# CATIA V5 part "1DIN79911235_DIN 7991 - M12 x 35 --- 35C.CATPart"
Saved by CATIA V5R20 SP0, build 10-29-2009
Part number: 1DIN79911235_DIN 7991 - M12 x 35 --- 35C
Revision: ANY
Definition: UNKNOWN
Nomenclature: 1DIN79911235_DIN 7991 - M12 x 35 --- 35C
Source: Unknown
Bounding box of the stored display mesh (mm): x 0 to 35, y -11.562 to 11.562, z -11.74 to 11.74
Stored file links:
  C:\Users\Utente\Desktop\IO LAVORO\3D X SITO CF\CUMSA\3D files RC\RC 328012\1DIN79911235_DIN 7991 - M12 x 35 --- 35C.CATPart
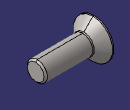
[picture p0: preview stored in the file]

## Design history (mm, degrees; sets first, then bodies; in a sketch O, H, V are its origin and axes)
Body1 "Hex" (main body)
  Solid1: solid without history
